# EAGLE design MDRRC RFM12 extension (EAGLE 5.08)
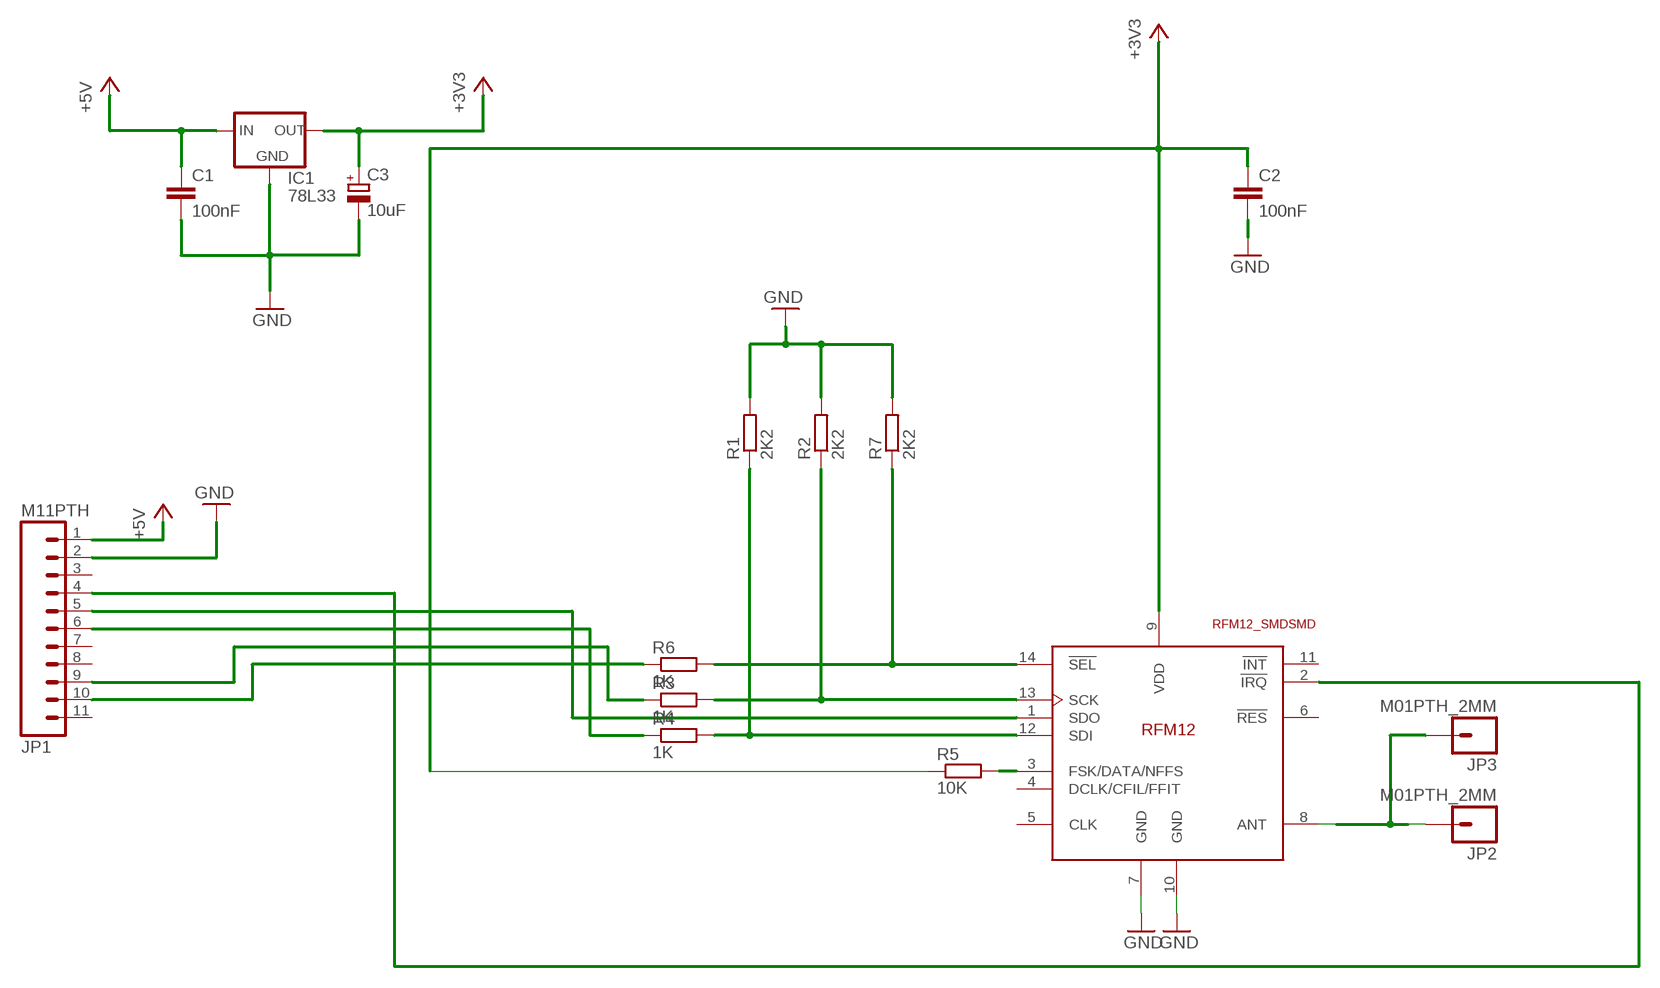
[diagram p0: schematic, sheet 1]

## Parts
C1  100nF  C-EU025-025X050  [C025-025X050]
C2  100nF  C-EU025-025X050  [C025-025X050]
C3  10uF  CPOL-EUE2.5-7  [E2,5-7]
IC1  78L33  78LXX  [78LXX]
JP1  M11PTH  [1X11]
JP2  M01PTH_2MM  [1X01_2MM]
JP3  M01PTH_2MM  [1X01_2MM]
R1  2K2  R-EU_0207/10  [0207/10]
R2  2K2  R-EU_0207/10  [0207/10]
R3  1K  R-EU_0207/10  [0207/10]
R4  1K  R-EU_0207/10  [0207/10]
R5  10K  R-EU_0207/10  [0207/10]
R6  1K  R-EU_0207/10  [0207/10]
R7  2K2  R-EU_0207/10  [0207/10]
U$1  RFM12_SMDSMD  [RFM12]

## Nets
+3V3: C3.+ IC1.OUT
+5V: C1.1 IC1.IN JP1.1
GND: C1.2 C2.2 C3.- IC1.GND JP1.2 R1.2 R2.2 R7.2 U$1.7(GND) U$1.10(GND)
N$1: JP2.1 JP3.1 U$1.8(ANT)
N$2: JP1.10 R6.1
N$3: R5.2 U$1.3(FSK/DATA/NFFS)
N$4: R2.1 R3.2 U$1.13(SCK)
N$5: R1.1 R4.2 U$1.12(SDI)
N$6: R6.2 R7.1 U$1.14(!SEL)
N$7: JP1.4 U$1.2(!IRQ)
N$8: JP1.9 R3.1
N$9: JP1.6 R4.1
N$10: JP1.5 U$1.1(SDO)
VDD: C2.1 R5.1 U$1.9(VDD) ; supply symbol labelled +3V3
Unconnected: JP1.3 JP1.7 JP1.8 JP1.11 U$1.4(DCLK/CFIL/FFIT) U$1.5(CLK) U$1.6(!RES) U$1.11(!INT)

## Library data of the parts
C1 C2 = rcl:C-EU: CAPACITOR, European symbol
C3 = resistor:CPOL-EU: POLARIZED CAPACITOR, European symbol
IC1 = v-reg:78LXX: VOLTAGE REGULATOR
JP1 = SparkFun:M11: Header 11 Standard 11-pin 0.1" header. Use with straight break away headers (SKU : PRT-00116), right angle break away headers (PRT-00553), swiss pins (PRT-00743), machine pins (PRT-00117), and female headers (PRT-00115).
JP2 JP3 = SparkFun:M01: Header 1
R1-R7 = resistor:R-EU_: RESISTOR, European symbol
U$1 = rfm_12:RFM12_SMD: RFM12 is a low costing ISM band transceiver module implemented with unique PLL. It works signal ranges from 315/433/868/915MHZ bands, comply with FCC, ETSI regulation. The SPI interface is used to communicate with microcontroller for parameter setting.

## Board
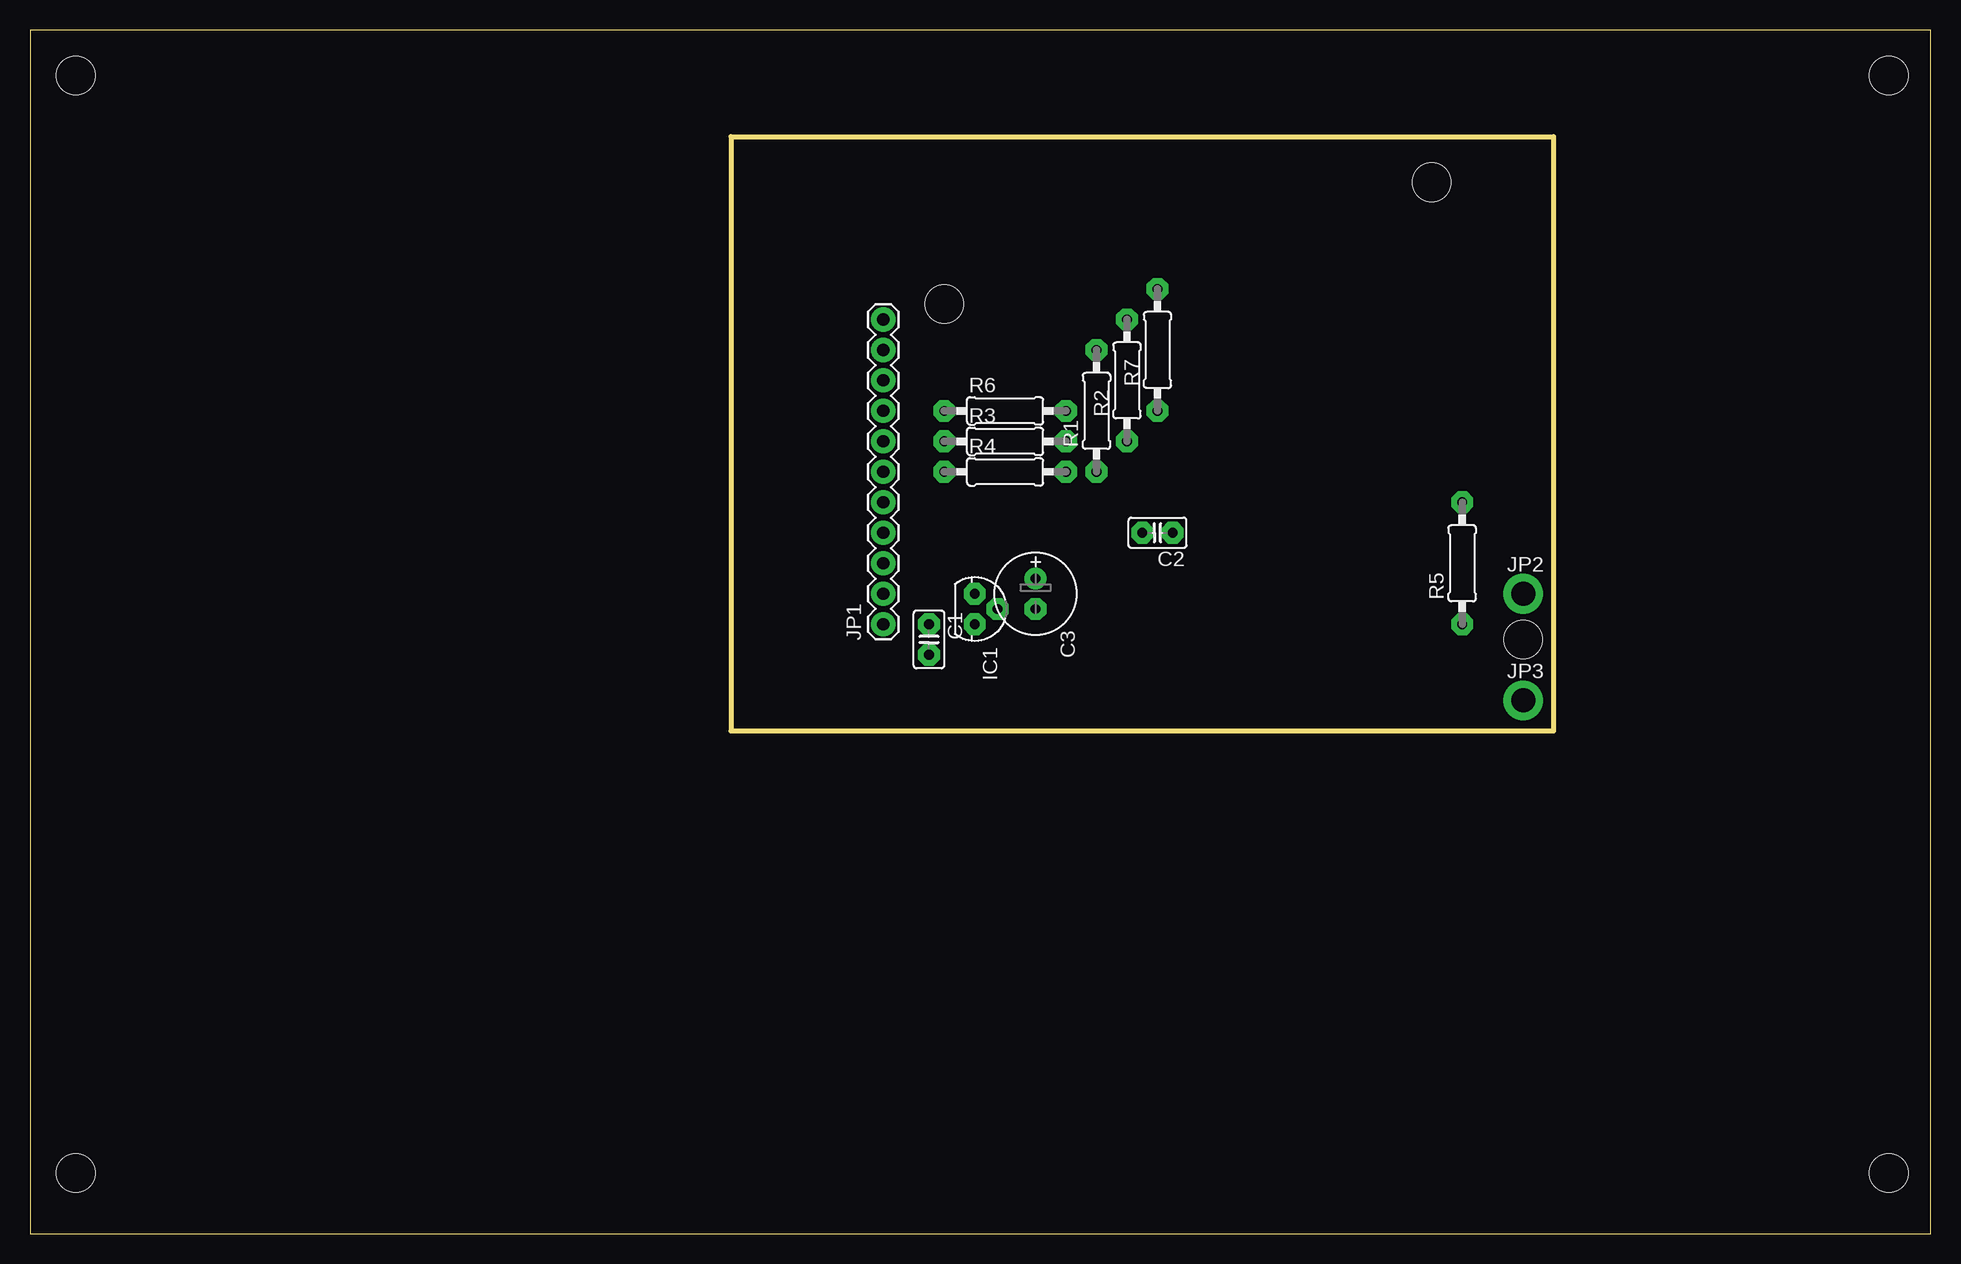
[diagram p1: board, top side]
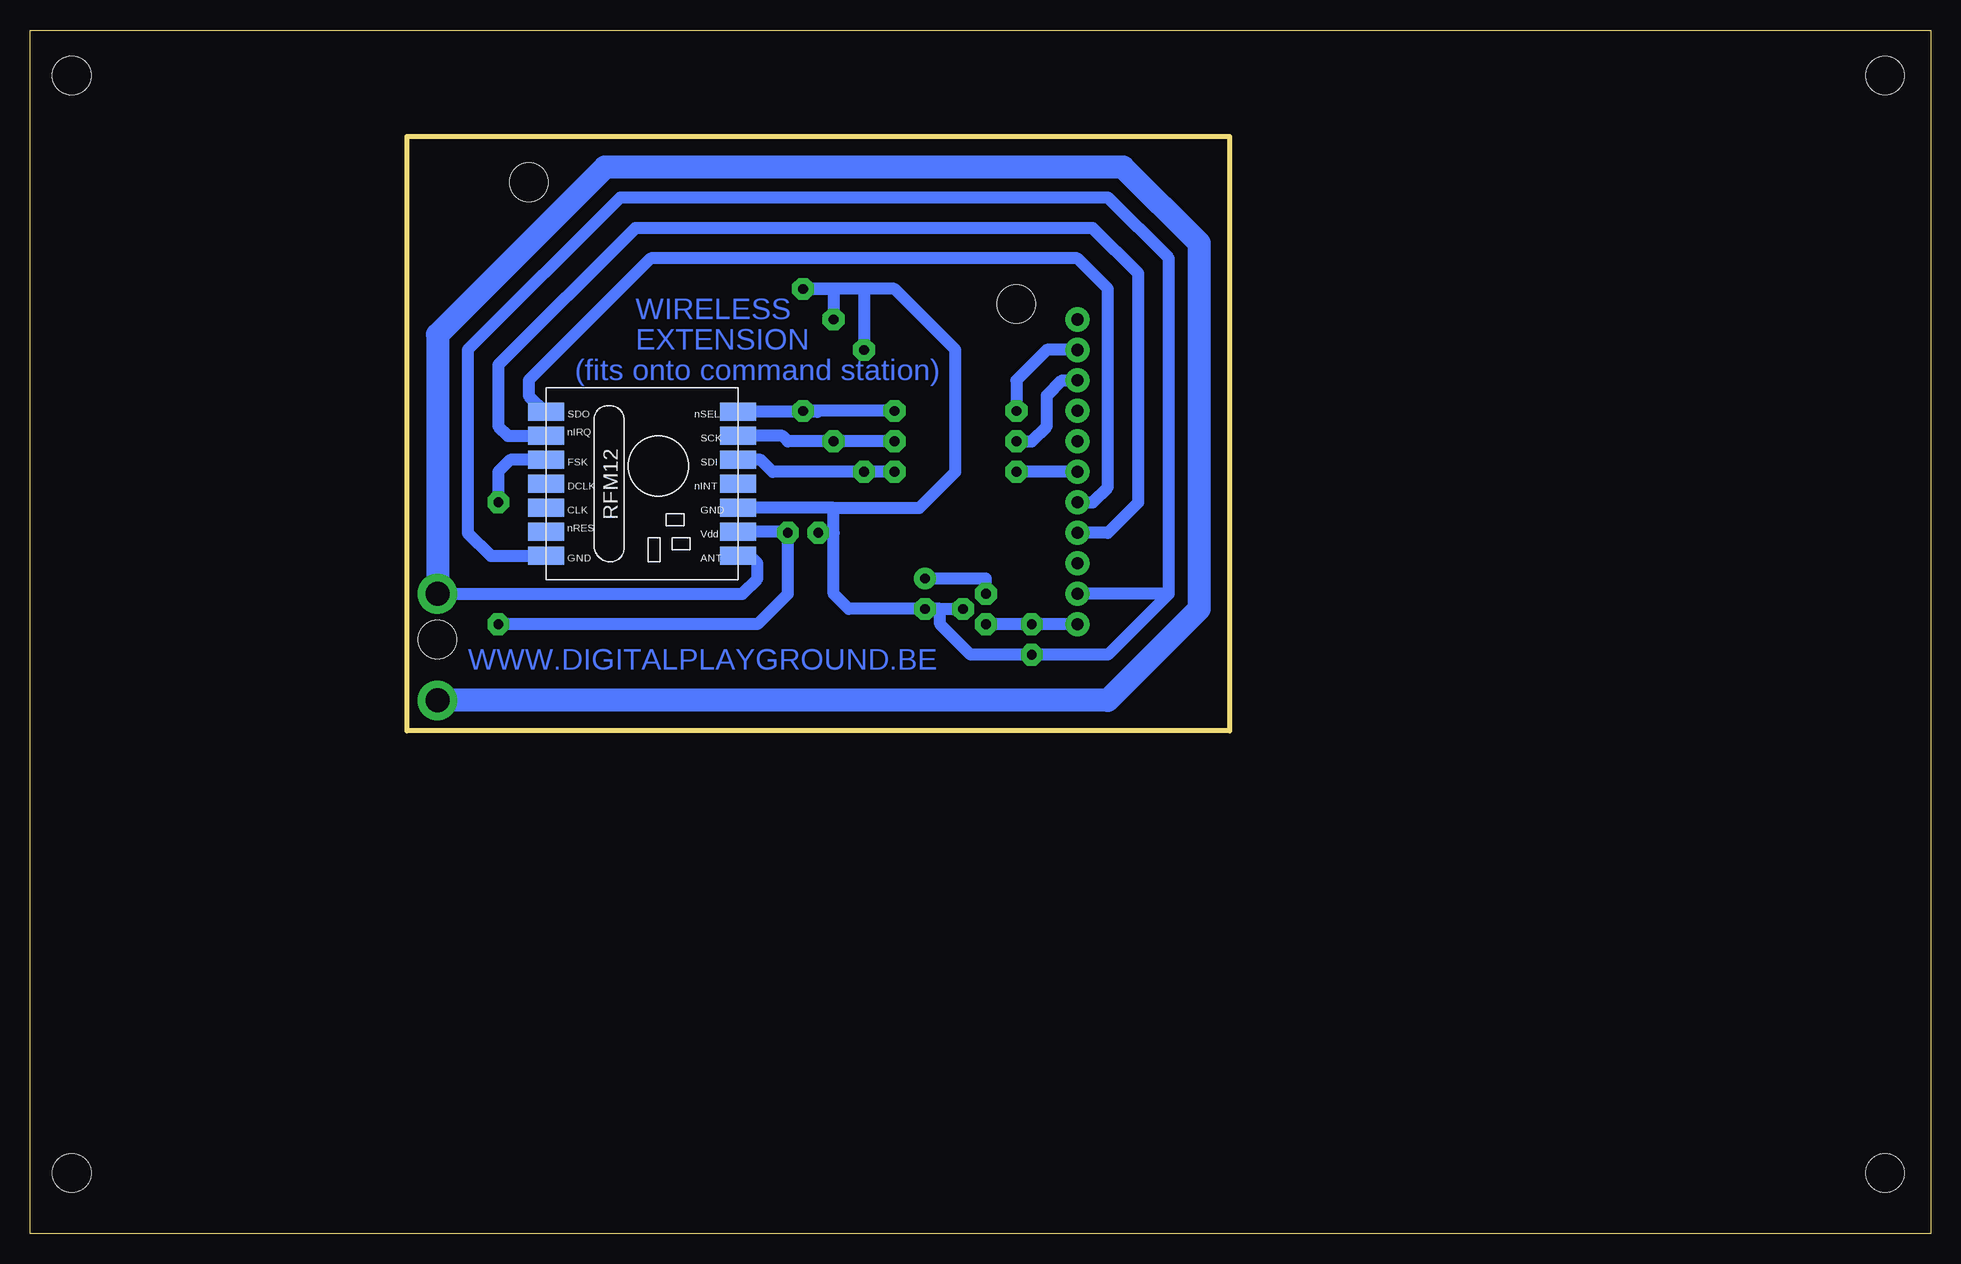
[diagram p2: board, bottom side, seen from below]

Size 158.42 x 100.32 mm. Coordinates in mm from the lower left corner, seen from the top.
Outline: 0,0 158.42,0 158.42,100.32 0,100.32 0,0
Outline: 58.42,91.44 58.42,41.91 127,41.91 127,91.44 58.42,91.44
Copper layers (1*16): Top 0.8mm / dielectric 1.3mm / Bottom 0.8mm
Design rules "DRC settings smallest": minimum track width 0.8mm, minimum drill 24mil, track to track 0.2mm, track to pad 0.2mm, pad to pad 0.2mm, via to via 0.2mm, smd to smd 8mil, copper to edge 0.3mm, drill to drill 0.3mm, minimum pad ring 0.5mm, minimum via ring 1mm, stop-mask expansion 4mil, vias tented up to drill 0mil, thermal gap 10mil
Holes 3.2 mm at 3.81,96.52 3.81,5.08 154.94,5.08 154.94,96.52 116.84,87.63 124.46,49.53 76.2,77.47

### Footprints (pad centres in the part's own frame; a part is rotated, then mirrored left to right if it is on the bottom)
C025-025X050 = drill 0.813 octagon: 1 -1.27,0; 2 1.27,0
E2,5-7 = drill 0.813 pad 1.6 round: + -1.27,0 | drill 0.813 pad 1.6 octagon: - 1.27,0
78LXX = drill 0.813 octagon: GND 0,1.905; IN 1.27,0; OUT -1.27,0
1X11 = drill 1.016 pad 1.88 round: 1 0,0; 2 2.54,0; 3 5.08,0; 4 7.62,0; 5 10.16,0; 6 12.7,0; 7 15.24,0; 8 17.78,0; 9 20.32,0; 10 22.86,0; 11 25.4,0
1X01_2MM = drill 2 pad 3.302 round: 1 0,0
0207/10 = drill 0.813 octagon: 1 -5.08,0; 2 5.08,0
RFM12 = smd 1.5 x 3: 1 -5,-10; 2 -3,-10; 3 -1,-10; 4 1,-10; 5 3,-10; 6 5,-10; 7 7,-10; 8 7,6; 9 5,6; 10 3,6; 11 1,6; 12 -1,6; 13 -3,6; 14 -5,6

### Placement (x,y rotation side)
C1  74.93,49.53 270 top
C2  93.98,58.42 180 top
C3  83.82,53.34 270 top
IC1  78.74,52.07 270 top
JP1  71.12,50.8 90 top
JP2  124.46,53.34 0 top
JP3  124.46,44.45 0 top
R1  88.9,68.58 90 top
R2  91.44,71.12 90 top
R3  81.28,66.04 0 top
R4  81.28,63.5 0 top
R5  119.38,55.88 90 top
R6  81.28,68.58 0 top
R7  93.98,73.66 90 top
U$1  105.41,63.5 270 bottom

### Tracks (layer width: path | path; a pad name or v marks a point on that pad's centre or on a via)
+3V3
  Bottom 1.016: C3.+ 78.74,54.61 IC1.OUT
+5V
  Bottom 1.016: IC1.IN C1.1 JP1.1
GND
  Bottom 1.016: 114.92,56.5 U$1.7 120,56.5 121.92,58.42 121.92,73.66 109.22,86.36 68.58,86.36 63.5,81.28 63.5,53.34 | 82.55,52.07 IC1.GND | 82.55,52.07 C3.- 90.17,52.07 91.44,53.34 91.44,58.42 | R2.2 91.44,78.74 R7.2 88.9,78.74 | 88.9,78.74 R1.2 | 91.44,58.42 C2.2 | 63.5,53.34 68.58,48.26 C1.2 80.01,48.26 82.55,50.8 82.55,52.07 | 63.5,53.34 JP1.2 | 88.9,78.74 86.36,78.74 81.28,73.66 81.28,63.5 84.28,60.5 91.44,60.5 | 91.44,60.5 U$1.10 | 91.44,58.42 91.44,60.5
N$1
  Bottom 1.016: U$1.8 98.41,56.5 97.79,55.88 97.79,54.61 99.06,53.34 JP2.1
  Bottom 1.93: JP2.1 124.46,74.93 110.49,88.9 67.31,88.9 60.96,82.55 60.96,52.07 68.58,44.45 JP3.1
N$2
  Bottom 1.016: R6.1 76.2,71.12 73.66,73.66 JP1.10
N$3
  Bottom 1.016: U$1.3 118.38,64.5 119.38,63.5 R5.2
N$4
  Bottom 1.016: U$1.13 95.71,66.5 95.25,66.04 R2.1 R3.2
N$5
  Bottom 1.016: R4.2 R1.1 96.52,63.5 97.52,64.5 U$1.12
N$6
  Bottom 1.016: U$1.14 92.79,68.5 R7.1 R6.2
N$7
  Bottom 1.016: JP1.4 68.58,58.42 66.04,60.96 66.04,80.01 69.85,83.82 107.95,83.82 119.38,72.39 119.38,67.31 118.57,66.5 U$1.2
N$8
  Bottom 1.016: R3.1 74.93,66.04 73.66,67.31 73.66,69.85 72.39,71.12 JP1.9
N$9
  Bottom 1.016: JP1.6 R4.1
N$10
  Bottom 1.016: JP1.5 69.85,60.96 68.58,62.23 68.58,78.74 71.12,81.28 106.68,81.28 116.84,71.12 116.84,69.85 115.49,68.5 U$1.1
VDD
  Bottom 1.016: U$1.9 95.33,58.5 C2.1 95.25,53.34 97.79,50.8 R5.1

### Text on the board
Bottom: WIRELESS | EXTENSION | (fits onto command station) | WWW.DIGITALPLAYGROUND.BE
